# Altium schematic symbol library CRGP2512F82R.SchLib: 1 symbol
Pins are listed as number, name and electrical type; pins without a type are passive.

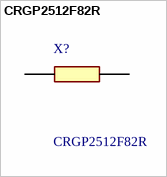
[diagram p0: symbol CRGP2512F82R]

## CRGP2512F82R
designator X?
Thick Film Resistors - SMD CRGP 2512 82R 1% SMD Resistor; Manufacturer_Name: TE Connectivity; Geometry.Height: 0.65mm
footprint RESC6432X65N
pins: 1, 2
